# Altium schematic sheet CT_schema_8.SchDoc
size 278 x 170 mm
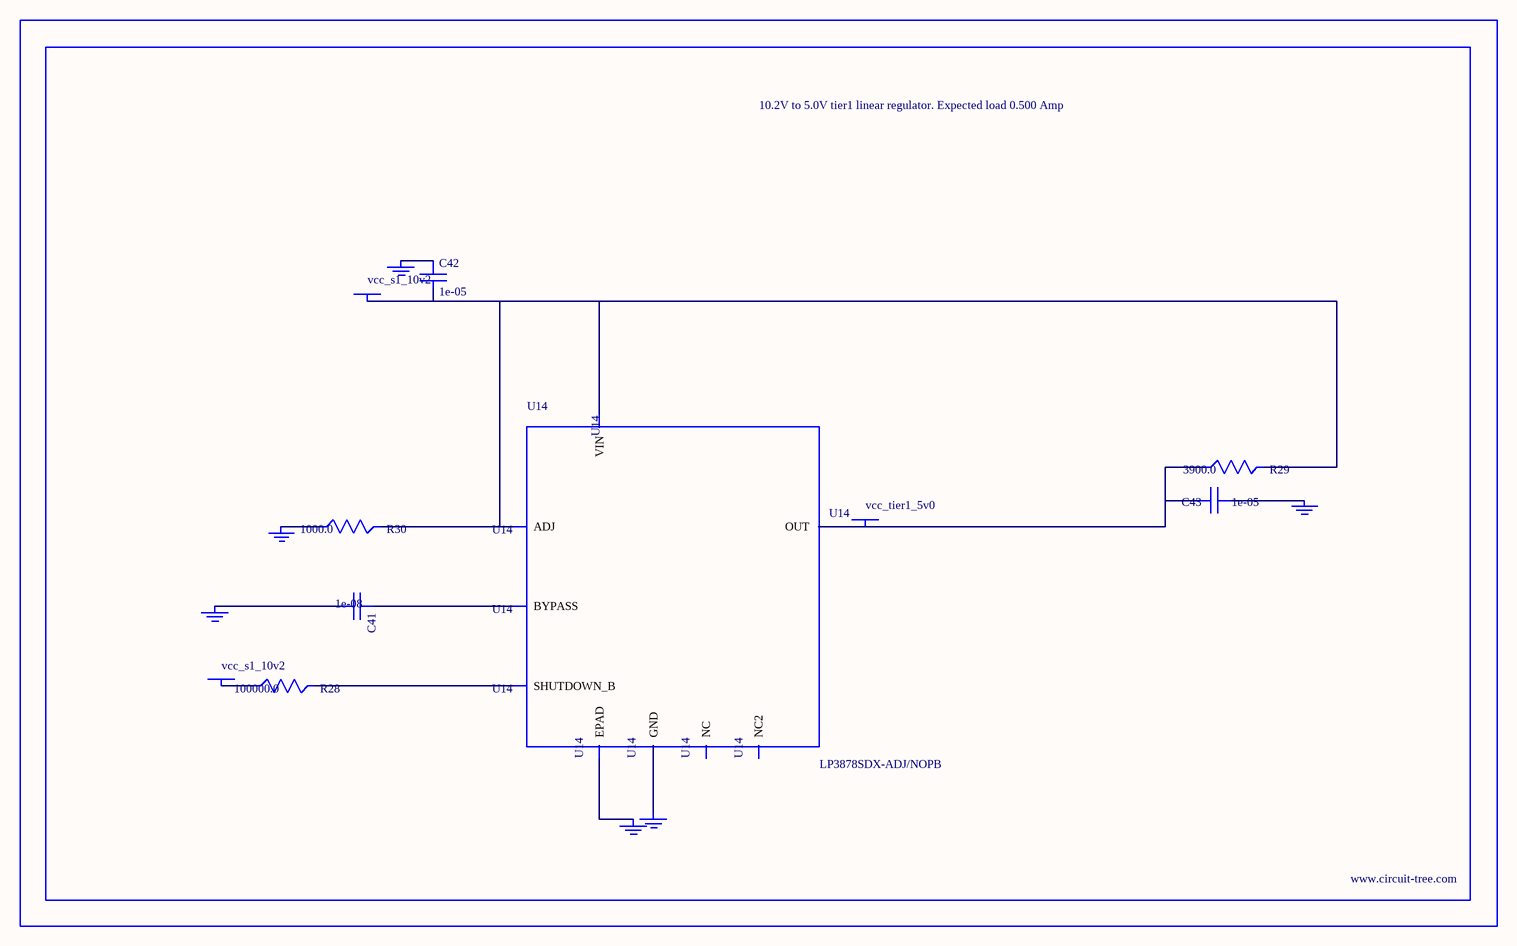
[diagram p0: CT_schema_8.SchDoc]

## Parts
BORDER7  (no value)
C41  1e-08  [C0402]
C42  1e-05  [C1206]
C43  1e-05  [C1210]
GND_INSTANCE_7_0  (no value)
GND_INSTANCE_7_1  (no value)
GND_INSTANCE_7_2  (no value)
GND_INSTANCE_7_3  (no value)
GND_INSTANCE_7_4  (no value)
GND_INSTANCE_7_5  (no value)
POWER_INSTANCE_7_0  vcc_s1_10v2
POWER_INSTANCE_7_1  vcc_s1_10v2
POWER_INSTANCE_7_2  vcc_tier1_5v0
R28  100000.0  [R0603]
R29  3900.0  [R0603]
R30  1000.0  [R0603]
U14  LP3878SDX-ADJ/NOPB  [WSON-8]

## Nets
NetC41_1: C41.1 U14.1(BYPASS)
NetC41_2: C41.2 GND_INSTANCE_7_0.0(GND)
NetC42_1: C42.1 GND_INSTANCE_7_1.0(GND)
NetC42_2: C42.2 POWER_INSTANCE_7_0.0(PWR) R29.2 R30.2 U14.4(VIN) U14.6(ADJ)
NetC43_1: C43.1 GND_INSTANCE_7_2.0(GND)
NetC43_2: C43.2 POWER_INSTANCE_7_2.0(PWR) R29.1 U14.5(OUT)
NetGND_INSTANCE_7_3_0: GND_INSTANCE_7_3.0(GND) R30.1
NetGND_INSTANCE_7_4_0: GND_INSTANCE_7_4.0(GND) U14.PAD(EPAD)
NetGND_INSTANCE_7_5_0: GND_INSTANCE_7_5.0(GND) U14.3(GND)
NetPOWER_INSTANCE_7_1_0: POWER_INSTANCE_7_1.0(PWR) R28.1
NetR28_2: R28.2 U14.8(SHUTDOWN_B)

Not connected (* = marked no-connect by the designer): U14 2(NC) 7(NC2)

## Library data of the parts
BORDER7 = BORDER_PAGE7
C41 = C0402C103K3RAC
C42 = C1206C106K3RACTU
C43 = GRM32DR61E106MA12L
GND_INSTANCE_7_0-GND_INSTANCE_7_5 = GND
POWER_INSTANCE_7_0-POWER_INSTANCE_7_2 = PWR
R28 = RC0603JR-07100KL
R29 = RC0603JR-073K9L
R30 = RC0603JR-071KL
